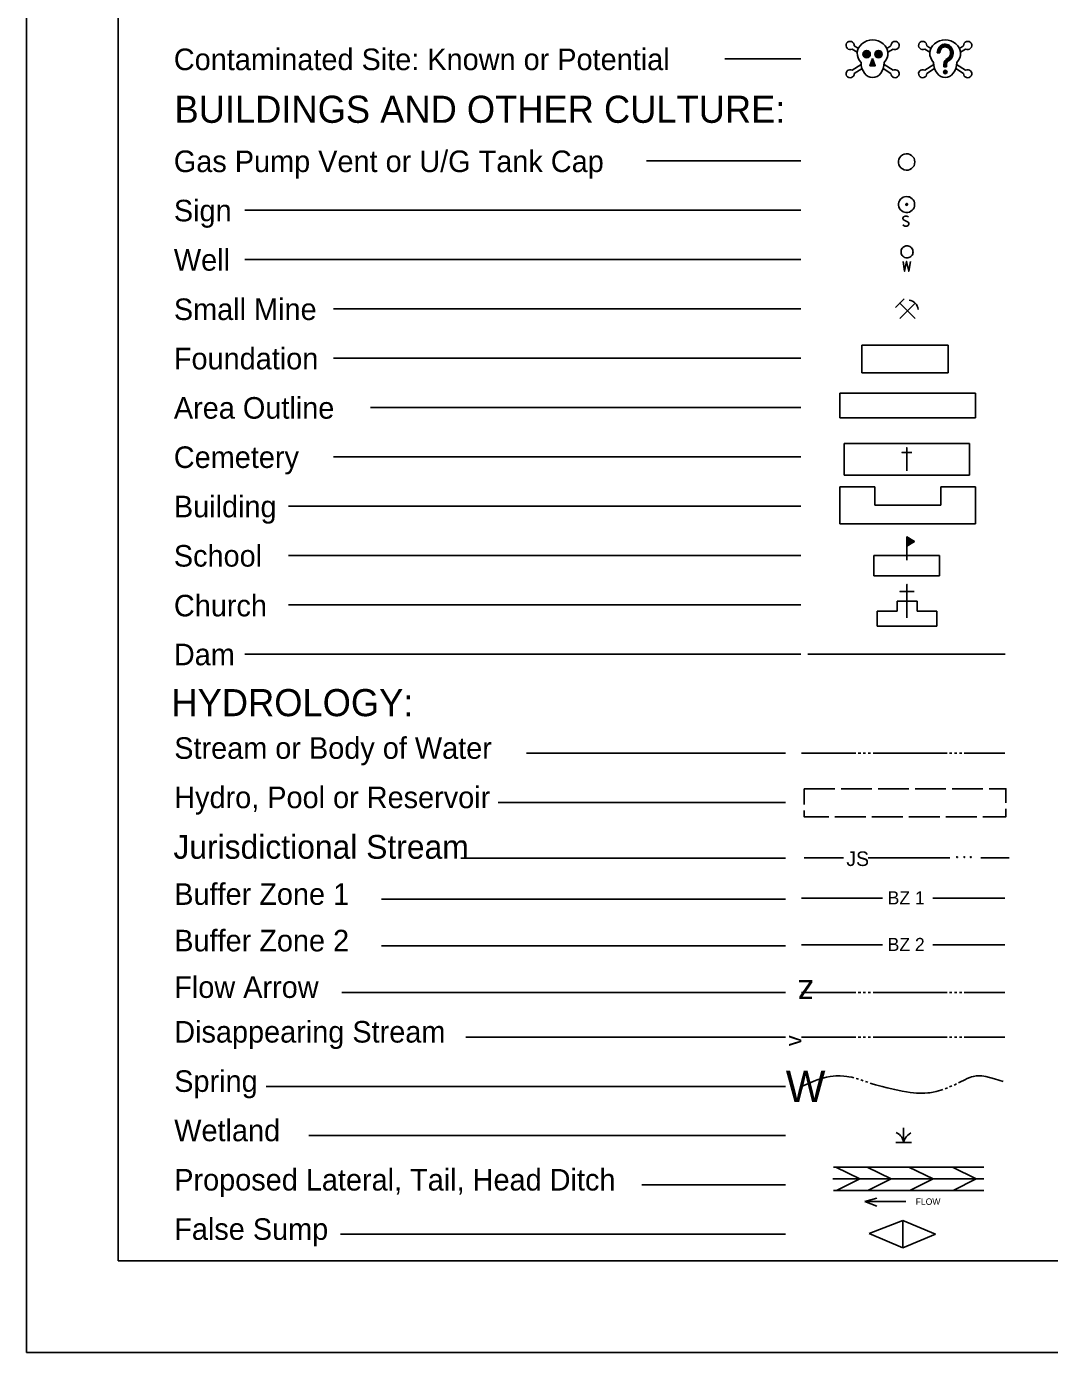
# Model space of a CAD drawing. Extents: x 754056.72 to 754059.56, y 596603.78 to 596605.61.
# Drawn here: x 754056.725 to 754057.422, y 596603.778 to 596604.682 of the extents above; entities that cross this region are included whole.
import ezdxf

# ---------------------------------------------------------------- set-up
doc = ezdxf.new("R2010")
doc.units = 0
for name, color, linetype in [('Sheet_Plan', 7, 'Continuous'), ('Sheet_Plot_Border_Outside_CELL', 7, 'Continuous'), ('Sheet_Symbology', 7, 'Continuous'), ('z - Construction', 7, 'Continuous')]:
    doc.layers.add(name, color=color, linetype=linetype)

msp = doc.modelspace()

# ---------------------------------------------------------------- linework, layer by layer
at = {"layer": 'Sheet_Plan'}
for q in [(754056.78733, 596605.54909), (754059.49562, 596603.84076)]:
    msp.add_line((754056.78734, 596603.84076), q, dxfattribs=at)
at = {"layer": 'Sheet_Plot_Border_Outside_CELL'}
msp.add_lwpolyline([(754056.72484, 596605.61159), (754059.55817, 596605.61159), (754059.55817, 596603.77826), (754056.72484, 596603.77826)], close=True, dxfattribs=at)
at = {"layer": 'Sheet_Symbology'}
for p, q in [((754057.28899, 596604.66932), (754057.29184, 596604.66753)), ((754057.31409, 596604.66932), (754057.31123, 596604.66753)), ((754057.33848, 596604.66932), (754057.34133, 596604.66753)), ((754057.36358, 596604.66932), (754057.36072, 596604.66753)), ((754057.25263, 596604.66031), (754057.20077, 596604.66031)), ((754057.28759, 596604.6671), (754057.29112, 596604.66488)), ((754057.30154, 596604.65989), (754057.30154, 596604.65989)), ((754057.31548, 596604.6671), (754057.31196, 596604.66488)), ((754057.33708, 596604.6671), (754057.34061, 596604.66488)), ((754057.34562, 596604.6644), (754057.34729, 596604.6644)), ((754057.35103, 596604.66074), (754057.35103, 596604.66074)), ((754057.36497, 596604.6671), (754057.36145, 596604.66488)), ((754057.29375, 596604.65654), (754057.28759, 596604.65267)), ((754057.29434, 596604.65381), (754057.28899, 596604.65045)), ((754057.30874, 596604.65381), (754057.31409, 596604.65045)), ((754057.30933, 596604.65654), (754057.31548, 596604.65267)), ((754057.34324, 596604.65654), (754057.33708, 596604.65267)), ((754057.34383, 596604.65381), (754057.33848, 596604.65045)), ((754057.35019, 596604.65652), (754057.35019, 596604.65505)), ((754057.35019, 596604.65505), (754057.35186, 596604.65505)), ((754057.35043, 596604.65652), (754057.35043, 596604.65505)), ((754057.35067, 596604.65652), (754057.35067, 596604.65505)), ((754057.35091, 596604.65652), (754057.35091, 596604.65505)), ((754057.35114, 596604.65652), (754057.35114, 596604.65505)), ((754057.35138, 596604.65652), (754057.35138, 596604.65505)), ((754057.35162, 596604.65652), (754057.35162, 596604.65505)), ((754057.35186, 596604.65652), (754057.35186, 596604.65505)), ((754057.35822, 596604.65381), (754057.36358, 596604.65045)), ((754057.35882, 596604.65654), (754057.36497, 596604.65267)), ((754057.25263, 596604.59079), (754057.14739, 596604.59079)), ((754057.25263, 596604.55716), (754056.87357, 596604.55716)), ((754057.25263, 596604.52353), (754056.87357, 596604.52353)), ((754057.25263, 596604.4899), (754056.9341, 596604.4899)), ((754057.32009, 596604.49386), (754057.31705, 596604.49083)), ((754057.32009, 596604.4834), (754057.33056, 596604.49386)), ((754057.32532, 596604.48863), (754057.32473, 596604.48922)), ((754057.32532, 596604.48863), (754057.33056, 596604.4834)), ((754057.29432, 596604.46507), (754057.35317, 596604.46507)), ((754057.29432, 596604.44626), (754057.29432, 596604.46507)), ((754057.35317, 596604.46507), (754057.35317, 596604.44626)), ((754057.25263, 596604.45627), (754056.9341, 596604.45627)), ((754057.35317, 596604.44626), (754057.29432, 596604.44626)), ((754057.37179, 596604.43239), (754057.27931, 596604.43239)), ((754057.27931, 596604.43239), (754057.27931, 596604.41557)), ((754057.37179, 596604.41557), (754057.37179, 596604.43239)), ((754057.25263, 596604.42263), (754056.95924, 596604.42263)), ((754057.27931, 596604.41557), (754057.37179, 596604.41557)), ((754057.28208, 596604.39813), (754057.36761, 596604.39813)), ((754057.28208, 596604.3766), (754057.28208, 596604.39813)), ((754057.36761, 596604.39813), (754057.36761, 596604.3766)), ((754057.25263, 596604.389), (754056.9341, 596604.389)), ((754057.36761, 596604.3766), (754057.28208, 596604.3766)), ((754057.30312, 596604.36855), (754057.27931, 596604.36855)), ((754057.27931, 596604.36855), (754057.27931, 596604.34333)), ((754057.30312, 596604.35594), (754057.30312, 596604.36855)), ((754057.37179, 596604.36855), (754057.34798, 596604.36855)), ((754057.34798, 596604.36855), (754057.34798, 596604.35594)), ((754057.37179, 596604.34333), (754057.37179, 596604.36855)), ((754057.25263, 596604.35537), (754056.90335, 596604.35537)), ((754057.34798, 596604.35594), (754057.30312, 596604.35594)), ((754057.27931, 596604.34333), (754057.37179, 596604.34333)), ((754057.25263, 596604.32174), (754056.90335, 596604.32174)), ((754057.3023, 596604.32174), (754057.34724, 596604.32174)), ((754057.3023, 596604.30778), (754057.3023, 596604.32174)), ((754057.34724, 596604.32174), (754057.34724, 596604.30778)), ((754057.34724, 596604.30778), (754057.3023, 596604.30778)), ((754057.33182, 596604.29061), (754057.31819, 596604.29061)), ((754057.31819, 596604.29061), (754057.31819, 596604.28382)), ((754057.33182, 596604.28382), (754057.33182, 596604.29061)), ((754057.25263, 596604.28811), (754056.90335, 596604.28811)), ((754057.31819, 596604.28382), (754057.30457, 596604.28382)), ((754057.30457, 596604.28382), (754057.30457, 596604.27358)), ((754057.34544, 596604.28382), (754057.33182, 596604.28382)), ((754057.34544, 596604.27358), (754057.34544, 596604.28382)), ((754057.30457, 596604.27358), (754057.34544, 596604.27358)), ((754057.25263, 596604.25448), (754056.87357, 596604.25448)), ((754057.25747, 596604.25448), (754057.39199, 596604.25448)), ((754057.24211, 596604.18689), (754057.06554, 596604.18689)), ((754057.25306, 596604.18689), (754057.29009, 596604.18689)), ((754057.29177, 596604.18689), (754057.29346, 596604.18689)), ((754057.29514, 596604.18689), (754057.29682, 596604.18689)), ((754057.2985, 596604.18689), (754057.30018, 596604.18689)), ((754057.30186, 596604.18689), (754057.35231, 596604.18689)), ((754057.35399, 596604.18689), (754057.35567, 596604.18689)), ((754057.35736, 596604.18689), (754057.35904, 596604.18689)), ((754057.36072, 596604.18689), (754057.3624, 596604.18689)), ((754057.36408, 596604.18689), (754057.39179, 596604.18689)), ((754057.25484, 596604.16263), (754057.27586, 596604.16263)), ((754057.25484, 596604.15204), (754057.25484, 596604.16263)), ((754057.28007, 596604.16263), (754057.30109, 596604.16263)), ((754057.30529, 596604.16263), (754057.32631, 596604.16263)), ((754057.33051, 596604.16263), (754057.35153, 596604.16263)), ((754057.35574, 596604.16263), (754057.37676, 596604.16263)), ((754057.24211, 596604.15325), (754057.04639, 596604.15325)), ((754057.29684, 596604.14359), (754057.27582, 596604.14359)), ((754057.32206, 596604.14359), (754057.30104, 596604.14359)), ((754057.34729, 596604.14359), (754057.32627, 596604.14359)), ((754057.37251, 596604.14359), (754057.35149, 596604.14359)), ((754057.24211, 596604.11526), (754057.0208, 596604.11526)), ((754057.24211, 596604.08732), (754056.96674, 596604.08732)), ((754057.25306, 596604.08804), (754057.3082, 596604.08804)), ((754057.39179, 596604.08804), (754057.34251, 596604.08804)), ((754057.24211, 596604.05558), (754056.96674, 596604.05558)), ((754057.25306, 596604.05613), (754057.3082, 596604.05613)), ((754057.39179, 596604.05613), (754057.34251, 596604.05613)), ((754057.24211, 596604.02385), (754056.9397, 596604.02385)), ((754057.25306, 596604.02385), (754057.29009, 596604.02385)), ((754057.29177, 596604.02385), (754057.29346, 596604.02385)), ((754057.29514, 596604.02385), (754057.29682, 596604.02385)), ((754057.2985, 596604.02385), (754057.30018, 596604.02385)), ((754057.30186, 596604.02385), (754057.35231, 596604.02385)), ((754057.35399, 596604.02385), (754057.35567, 596604.02385)), ((754057.35736, 596604.02385), (754057.35904, 596604.02385)), ((754057.36072, 596604.02385), (754057.3624, 596604.02385)), ((754057.36408, 596604.02385), (754057.39179, 596604.02385)), ((754057.24211, 596603.99339), (754057.02432, 596603.99339)), ((754057.25306, 596603.99339), (754057.29009, 596603.99339)), ((754057.29177, 596603.99339), (754057.29346, 596603.99339)), ((754057.29514, 596603.99339), (754057.29682, 596603.99339)), ((754057.2985, 596603.99339), (754057.30018, 596603.99339)), ((754057.30186, 596603.99339), (754057.35231, 596603.99339)), ((754057.35399, 596603.99339), (754057.35567, 596603.99339)), ((754057.35736, 596603.99339), (754057.35904, 596603.99339)), ((754057.36072, 596603.99339), (754057.3624, 596603.99339)), ((754057.36408, 596603.99339), (754057.39179, 596603.99339)), ((754057.2968, 596603.96303), (754057.2984, 596603.96249)), ((754057.24211, 596603.95975), (754056.88818, 596603.95975)), ((754057.35094, 596603.95812), (754057.3525, 596603.95875)), ((754057.35408, 596603.95936), (754057.35561, 596603.96001)), ((754057.32261, 596603.92156), (754057.32261, 596603.93144)), ((754057.24211, 596603.92612), (754056.91721, 596603.92612)), ((754057.31729, 596603.92156), (754057.32801, 596603.92156)), ((754057.27487, 596603.90468), (754057.37747, 596603.90468)), ((754057.27639, 596603.90468), (754057.29285, 596603.89661)), ((754057.29777, 596603.90468), (754057.31422, 596603.89661)), ((754057.32627, 596603.90468), (754057.34279, 596603.89661)), ((754057.35609, 596603.90468), (754057.37224, 596603.89661)), ((754057.24211, 596603.89249), (754057.14428, 596603.89249)), ((754057.27443, 596603.89661), (754057.37747, 596603.89661)), ((754057.29285, 596603.89661), (754057.27685, 596603.88879)), ((754057.31422, 596603.89661), (754057.29829, 596603.88879)), ((754057.34279, 596603.89661), (754057.32686, 596603.88879)), ((754057.37224, 596603.89661), (754057.35654, 596603.88879)), ((754057.27487, 596603.88879), (754057.37747, 596603.88879)), ((754057.29631, 596603.88123), (754057.30439, 596603.8835)), ((754057.29631, 596603.88123), (754057.32431, 596603.88123)), ((754057.29631, 596603.88123), (754057.30439, 596603.87795)), ((754057.32206, 596603.8683), (754057.29924, 596603.85943)), ((754057.32206, 596603.84972), (754057.32206, 596603.8683)), ((754057.34445, 596603.85901), (754057.32206, 596603.8683)), ((754057.24211, 596603.85886), (754056.93896, 596603.85886)), ((754057.29924, 596603.85943), (754057.32206, 596603.84972)), ((754057.32206, 596603.84972), (754057.34445, 596603.85901))]:
    msp.add_line(p, q, dxfattribs=at)
for points in [[(754057.30154, 596604.66074), (754057.2997, 596604.6557), (754057.30338, 596604.6557)], [(754057.30154, 596604.65989), (754057.30012, 596604.656), (754057.30296, 596604.656)], [(754057.30154, 596604.65903), (754057.30054, 596604.65629), (754057.30254, 596604.65629)], [(754057.30154, 596604.65817), (754057.30096, 596604.65659), (754057.30212, 596604.65659)], [(754057.30154, 596604.65732), (754057.30138, 596604.65688), (754057.3017, 596604.65688)]]:
    msp.add_lwpolyline(points, close=True, dxfattribs=at)
for points in [[(754057.33037, 596604.59008), (754057.33007, 596604.59142), (754057.32978, 596604.59261), (754057.32903, 596604.59365), (754057.32799, 596604.59454), (754057.32695, 596604.59514), (754057.32575, 596604.59559), (754057.32441, 596604.59559), (754057.32307, 596604.59544), (754057.32188, 596604.59484), (754057.32084, 596604.5941), (754057.3201, 596604.5932), (754057.3195, 596604.59201), (754057.3192, 596604.59067), (754057.3192, 596604.58948), (754057.3195, 596604.58814), (754057.3201, 596604.58695), (754057.32084, 596604.58605), (754057.32188, 596604.58531), (754057.32307, 596604.58471), (754057.32441, 596604.58456), (754057.32575, 596604.58456), (754057.32695, 596604.58501), (754057.32799, 596604.58561), (754057.32903, 596604.5865), (754057.32978, 596604.58754), (754057.33007, 596604.58874), (754057.33037, 596604.59008)], [(754057.33022, 596604.56107), (754057.3301, 596604.56216), (754057.32978, 596604.56325), (754057.32923, 596604.56423), (754057.32847, 596604.565), (754057.32759, 596604.56565), (754057.32661, 596604.5662), (754057.32563, 596604.56642), (754057.32442, 596604.56653), (754057.32333, 596604.56631), (754057.32235, 596604.56598), (754057.32137, 596604.56543), (754057.3206, 596604.56467), (754057.31995, 596604.56369), (754057.31951, 596604.5627), (754057.31929, 596604.56161), (754057.31929, 596604.56052), (754057.31951, 596604.55943), (754057.31995, 596604.55844), (754057.3206, 596604.55746), (754057.32137, 596604.5567), (754057.32235, 596604.55615), (754057.32333, 596604.55582), (754057.32442, 596604.5556), (754057.32563, 596604.55571), (754057.32661, 596604.55593), (754057.32759, 596604.55648), (754057.32847, 596604.55713), (754057.32923, 596604.5579), (754057.32978, 596604.55888), (754057.3301, 596604.55997), (754057.33022, 596604.56107)], [(754057.32497, 596604.56172), (754057.32464, 596604.56172), (754057.32432, 596604.5615), (754057.3241, 596604.56117), (754057.32421, 596604.56085), (754057.32442, 596604.56052), (754057.32475, 596604.56041), (754057.32508, 596604.56052), (754057.3253, 596604.56074), (754057.32541, 596604.56117), (754057.3253, 596604.5615), (754057.32497, 596604.56172)], [(754057.32603, 596604.55265), (754057.32497, 596604.55312), (754057.32376, 596604.55312), (754057.32264, 596604.55265), (754057.32217, 596604.5518), (754057.32217, 596604.55148), (754057.3227, 596604.55069), (754057.32577, 596604.5491), (754057.3263, 596604.54836), (754057.32625, 596604.54772), (754057.32577, 596604.54687), (754057.32487, 596604.5464), (754057.3236, 596604.5464), (754057.32301, 596604.54661), (754057.32217, 596604.54719)], [(754057.3292, 596604.52875), (754057.32907, 596604.52948), (754057.32894, 596604.53021), (754057.32861, 596604.53087), (754057.32815, 596604.53147), (754057.32762, 596604.532), (754057.32702, 596604.5324), (754057.32629, 596604.53266), (754057.32557, 596604.53286), (754057.32484, 596604.53286), (754057.32411, 596604.53279), (754057.32338, 596604.53253), (754057.32279, 596604.5322), (754057.32219, 596604.53173), (754057.32166, 596604.53121), (754057.32133, 596604.53054), (754057.32106, 596604.52988), (754057.32093, 596604.52915), (754057.32093, 596604.52836), (754057.32106, 596604.52763), (754057.32133, 596604.52697), (754057.32166, 596604.52631), (754057.32219, 596604.52578), (754057.32279, 596604.52531), (754057.32338, 596604.52498), (754057.32411, 596604.52472), (754057.32484, 596604.52465), (754057.32557, 596604.52465), (754057.32629, 596604.52485), (754057.32702, 596604.52512), (754057.32762, 596604.52551), (754057.32815, 596604.52604), (754057.32861, 596604.52664), (754057.32894, 596604.5273), (754057.32907, 596604.52803), (754057.3292, 596604.52875)], [(754057.32234, 596604.52227), (754057.32339, 596604.51554), (754057.32477, 596604.52227), (754057.32615, 596604.51554), (754057.32731, 596604.52227)], [(754057.32532, 596604.48863), (754057.32009, 596604.49386), (754057.32304, 596604.49682)], [(754057.33267, 596604.48956), (754057.33241, 596604.49074), (754057.33199, 596604.49184), (754057.3314, 596604.49285), (754057.33064, 596604.4937), (754057.3298, 596604.49454), (754057.32878, 596604.49513), (754057.32769, 596604.49564), (754057.32659, 596604.49589)], [(754057.32488, 596604.3795), (754057.32488, 596604.39527), (754057.32488, 596604.39191), (754057.32153, 596604.39191), (754057.32823, 596604.39191)], [(754057.32484, 596604.31861), (754057.32484, 596604.33437), (754057.33011, 596604.33127), (754057.32484, 596604.32817), (754057.32515, 596604.32866), (754057.32515, 596604.33394), (754057.32949, 596604.33121), (754057.32546, 596604.32885), (754057.32552, 596604.33344), (754057.329, 596604.33121), (754057.32583, 596604.32941), (754057.32583, 596604.33288), (754057.32844, 596604.33121), (754057.3262, 596604.32997), (754057.3262, 596604.33233), (754057.32788, 596604.33127), (754057.32651, 596604.33046), (754057.32651, 596604.33177), (754057.32738, 596604.33127), (754057.32682, 596604.33096), (754057.32676, 596604.33133), (754057.32695, 596604.33127)], [(754057.325, 596604.27926), (754057.325, 596604.30196), (754057.325, 596604.29713), (754057.32018, 596604.29713), (754057.32983, 596604.29713)], [(754057.38096, 596604.16263), (754057.39244, 596604.16263), (754057.39244, 596604.15309)], [(754057.27162, 596604.14359), (754057.25484, 596604.14359), (754057.25484, 596604.14783)], [(754057.39244, 596604.14888), (754057.39244, 596604.14359), (754057.37671, 596604.14359)], [(754057.25484, 596604.11559), (754057.28176, 596604.11559)], [(754057.29864, 596604.11559), (754057.32222, 596604.11559)], [(754057.32222, 596604.11559), (754057.35416, 596604.11559)], [(754057.37535, 596604.11559), (754057.39455, 596604.11559)], [(754057.25308, 596603.95975), (754057.25785, 596603.96175), (754057.26264, 596603.96377), (754057.26384, 596603.96423), (754057.26596, 596603.96497), (754057.2676, 596603.96541), (754057.27006, 596603.96598), (754057.27254, 596603.96642), (754057.27462, 596603.96667), (754057.27647, 596603.96682), (754057.27809, 596603.96686), (754057.27952, 596603.96686), (754057.28202, 596603.96671), (754057.28389, 596603.96652), (754057.28528, 596603.96631), (754057.28736, 596603.96591), (754057.28879, 596603.96558)], [(754057.29043, 596603.96514), (754057.29121, 596603.9649), (754057.29203, 596603.96465)], [(754057.29362, 596603.96413), (754057.29432, 596603.9639), (754057.29522, 596603.96358)], [(754057.36021, 596603.96211), (754057.36101, 596603.96251), (754057.36431, 596603.96423), (754057.36599, 596603.96505), (754057.36774, 596603.96577), (754057.36906, 596603.96621), (754057.37024, 596603.9665), (754057.37129, 596603.96671), (754057.37222, 596603.96686), (754057.37386, 596603.96696), (754057.37507, 596603.96696), (754057.37598, 596603.9669), (754057.37732, 596603.96671), (754057.37865, 596603.96642), (754057.38462, 596603.96478), (754057.39057, 596603.96312)], [(754057.29999, 596603.96194), (754057.30128, 596603.9615), (754057.30363, 596603.96081), (754057.30815, 596603.95961), (754057.31155, 596603.95875), (754057.31666, 596603.95757), (754057.32181, 596603.9565), (754057.32467, 596603.95599), (754057.32719, 596603.95561), (754057.32942, 596603.95536), (754057.33138, 596603.95519), (754057.33308, 596603.95511), (754057.33459, 596603.95507), (754057.3372, 596603.95511), (754057.33915, 596603.95524), (754057.34062, 596603.9554), (754057.34279, 596603.95572), (754057.34493, 596603.95618), (754057.34655, 596603.95662), (754057.34796, 596603.95704), (754057.34937, 596603.95755)], [(754057.35717, 596603.96066), (754057.3575, 596603.96081), (754057.3587, 596603.96135)], [(754057.32261, 596603.92156), (754057.32236, 596603.92275), (754057.32202, 596603.92393), (754057.32143, 596603.92503), (754057.32067, 596603.92604), (754057.31983, 596603.92697), (754057.31881, 596603.92764), (754057.31772, 596603.92823)], [(754057.32261, 596603.92156), (754057.32312, 596603.92283), (754057.32371, 596603.9241), (754057.32447, 596603.92528), (754057.3254, 596603.92629), (754057.32641, 596603.92722), (754057.32751, 596603.92807)]]:
    msp.add_lwpolyline(points, dxfattribs=at)
for centre, radius in [((754057.29748, 596604.66361), 0.0025), ((754057.29748, 596604.66361), 0.0022), ((754057.29748, 596604.66361), 0.00191), ((754057.29748, 596604.66361), 0.00161), ((754057.29748, 596604.66361), 0.00132), ((754057.29748, 596604.66361), 0.00102), ((754057.29748, 596604.66361), 0.00073), ((754057.29748, 596604.66361), 0.000435), ((754057.29748, 596604.66361), 0.000141), ((754057.3056, 596604.66361), 0.0025), ((754057.3056, 596604.66361), 0.0022), ((754057.3056, 596604.66361), 0.00191), ((754057.3056, 596604.66361), 0.00161), ((754057.3056, 596604.66361), 0.00132), ((754057.3056, 596604.66361), 0.00102), ((754057.3056, 596604.66361), 0.00073), ((754057.3056, 596604.66361), 0.000435), ((754057.3056, 596604.66361), 0.000141), ((754057.35108, 596604.65143), 0.00119), ((754057.35108, 596604.65143), 0.000927), ((754057.35108, 596604.65143), 0.000657), ((754057.35108, 596604.65143), 0.000392), ((754057.35108, 596604.65143), 0.000127)]:
    msp.add_circle(centre, radius, dxfattribs=at)
for centre, start, end in [((754057.28621, 596604.66952), 355.89762, 299.80617), ((754057.31687, 596604.66952), 240.19383, 184.10238), ((754057.33569, 596604.66952), 355.89762, 299.80617), ((754057.36636, 596604.66952), 240.19383, 184.10238), ((754057.28621, 596604.65025), 60.19383, 4.10238), ((754057.31687, 596604.65025), 175.89762, 119.80617), ((754057.33569, 596604.65025), 60.19383, 4.10238), ((754057.36636, 596604.65025), 175.89762, 119.80617)]:
    msp.add_arc(centre, 0.00279, start, end, dxfattribs=at)
for centre, major_axis, ratio, start_param, end_param in [((754057.30154, 596604.66405), (0.01046, 0), 0.885014, 5.564242, 10.143721), ((754057.35103, 596604.66405), (0.01046, 0), 0.885014, 5.564242, 10.143721), ((754057.35103, 596604.6644), (0, 0.006), 0.9, 3.567618, 7.853982), ((754057.35103, 596604.6644), (0, 0.00574), 0.9, 3.567618, 7.853982), ((754057.35103, 596604.6644), (0, 0.00547), 0.9, 3.567618, 7.853982), ((754057.35103, 596604.6644), (0, 0.00521), 0.9, 3.567618, 7.853982), ((754057.35103, 596604.6644), (0, 0.00494), 0.9, 3.567618, 7.853982), ((754057.35103, 596604.6644), (0, 0.00468), 0.9, 3.567618, 7.853982), ((754057.35103, 596604.6644), (0, 0.00441), 0.9, 3.567618, 7.853982), ((754057.35103, 596604.6644), (0, 0.00415), 0.9, 3.567618, 7.853982), ((754057.35424, 596604.65652), (0, 0.0045), 0.9, 0.426026, 1.570796), ((754057.35424, 596604.65652), (0, 0.00424), 0.9, 0.426026, 1.570796), ((754057.35424, 596604.65652), (0, 0.00397), 0.9, 0.426026, 1.570796), ((754057.35424, 596604.65652), (0, 0.00371), 0.9, 0.426026, 1.570796), ((754057.35424, 596604.65652), (0, 0.00344), 0.9, 0.426026, 1.570796), ((754057.35424, 596604.65652), (0, 0.00318), 0.9, 0.426026, 1.570796), ((754057.35424, 596604.65652), (0, 0.00291), 0.9, 0.426026, 1.570796), ((754057.35424, 596604.65652), (0, 0.00265), 0.9, 0.426026, 1.570796), ((754057.30154, 596604.65806), (0, -0.01046), 0.752542, 4.722735, 7.843636), ((754057.35103, 596604.65806), (0, -0.01046), 0.752542, 4.722735, 7.843636)]:
    msp.add_ellipse(centre, major_axis=major_axis, ratio=ratio, start_param=start_param, end_param=end_param, dxfattribs=at)
for centre in [(754057.35911, 596604.11606), (754057.36408, 596604.11606), (754057.36843, 596604.11606)]:
    msp.add_ellipse(centre, major_axis=(0, 0.000331), ratio=0.938496, dxfattribs=at)
at = {"layer": 'z - Construction'}
for p, q in [((754056.72484, 596605.61159), (754056.72484, 596603.77826)), ((754056.72484, 596603.77826), (754059.55817, 596603.77826))]:
    msp.add_line(p, q, dxfattribs=at)

# ---------------------------------------------------------------- texts
at = {"layer": 'Sheet_Symbology'}
for s, height, p in [('Contaminated Site: Known or Potential', 0.0147137, (754056.82524, 596604.6527)), ('BUILDINGS AND OTHER CULTURE:', 0.0184972, (754056.82571, 596604.61677)), ('Gas Pump Vent or U/G Tank Cap', 0.0147137, (754056.82524, 596604.58318)), ('Sign', 0.014714, (754056.82527, 596604.54957)), ('Well', 0.014714, (754056.82527, 596604.51594)), ('Small Mine', 0.014714, (754056.82527, 596604.48229)), ('Foundation', 0.014714, (754056.82527, 596604.44866)), ('Area Outline', 0.0147137, (754056.82527, 596604.41503)), ('Cemetery', 0.014714, (754056.82524, 596604.38141)), ('Building', 0.014714, (754056.82527, 596604.34778)), ('School', 0.014714, (754056.82524, 596604.31415)), ('Church', 0.014714, (754056.82529, 596604.28021)), ('Dam', 0.014714, (754056.82527, 596604.24689)), ('HYDROLOGY:', 0.018497, (754056.82361, 596604.21215)), ('Stream or Body of Water', 0.0147137, (754056.82552, 596604.18308)), ('Hydro, Pool or Reservoir', 0.0147137, (754056.82552, 596604.14945)), ('Jurisdictional Stream', 0.0162204, (754056.82496, 596604.11493)), ('JS', 0.00993, (754057.28363, 596604.11)), ('Buffer Zone 1', 0.0147137, (754056.82552, 596604.08351)), ('BZ 1', 0.008937, (754057.31182, 596604.08383)), ('Buffer Zone 2', 0.0147137, (754056.82552, 596604.05178)), ('BZ 2', 0.008937, (754057.31182, 596604.05204)), ('Flow Arrow', 0.014714, (754056.82552, 596604.02005)), ('Disappearing Stream', 0.0147137, (754056.82552, 596603.98958)), ('Spring', 0.014714, (754056.82552, 596603.95595)), ('W', 0.02144, (754057.24236, 596603.94903)), ('Wetland', 0.014714, (754056.82552, 596603.92232)), ('Proposed Lateral, Tail, Head Ditch', 0.0147137, (754056.82552, 596603.88869)), ('FLOW', 0.00436, (754057.33093, 596603.87896)), ('False Sump', 0.014714, (754056.82552, 596603.85506))]:
    msp.add_text(s, height=height, dxfattribs=at).set_placement(p)
for s, height, rotation, p in [('z', 0.01682, 180.00002, (754057.26149, 596604.03226)), ('v', 0.0111, 89.75915, (754057.25306, 596603.9871))]:
    msp.add_text(s, height=height, rotation=rotation, dxfattribs=at).set_placement(p)

doc.saveas('drawing.dxf')
